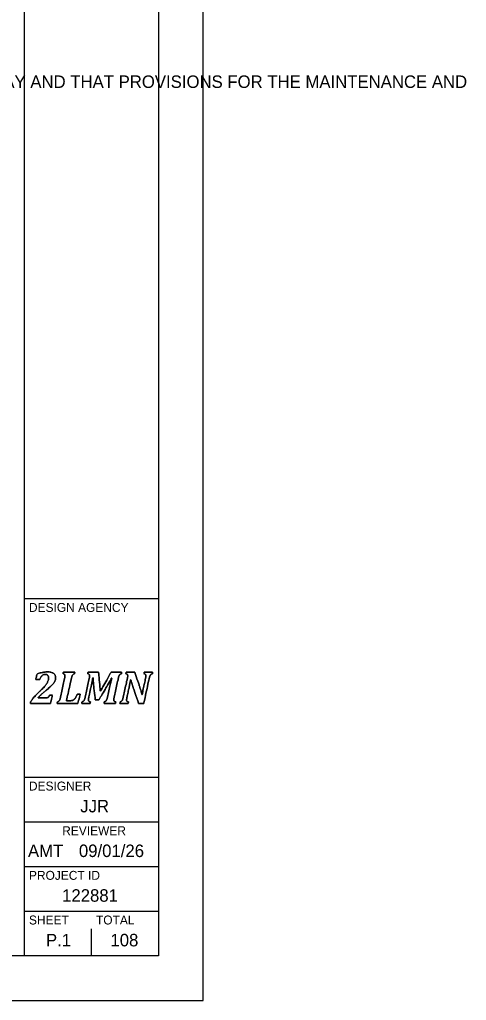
# Model space of a CAD drawing. Extents: x 0 to 36.9, y 0 to 22.
# Drawn here: x 31.95 to 36.95, y 0 to 10.98 of the extents above; entities that cross this region are included whole.
import ezdxf

# ---------------------------------------------------------------- set-up
doc = ezdxf.new("R2010")
doc.units = 0
for name, color, linetype in [('Default', 7, 'Continuous'), ('SH_Border', 7, 'Continuous'), ('SH_Cut_Line', 7, 'Continuous'), ('SH_Data', 7, 'Continuous')]:
    doc.layers.add(name, color=color, linetype=linetype)

msp = doc.modelspace()

# ---------------------------------------------------------------- linework, layer by layer
at = {"layer": 'SH_Border'}
for p, q in [((32, 0.5), (32, 21.5)), ((32, 4.5), (33.5, 4.5)), ((32, 2.5), (33.5, 2.5)), ((32, 2), (33.5, 2)), ((32, 1.5), (33.5, 1.5)), ((32, 1), (33.5, 1))]:
    msp.add_line(p, q, dxfattribs=at)
msp.add_lwpolyline([(1.5, 21.5), (33.5, 21.5), (33.5, 0.5), (1.5, 0.5)], close=True, dxfattribs=at)
at = {"layer": 'SH_Cut_Line'}
msp.add_lwpolyline([(0, 0), (34, 0), (34, 22), (0, 22)], close=True, dxfattribs=at)
at = {"layer": 'SH_Data'}
for p, q in [((32.75, 3.5), (32.75, 3.5)), ((32.75, 0.5), (32.75, 0.8)), ((32.375, 0.675), (32.375, 0.675))]:
    msp.add_line(p, q, dxfattribs=at)
for points in [[(32.237, 3.388), (32.246, 3.388), (32.253, 3.389), (32.258, 3.39), (32.263, 3.392), (32.267, 3.394), (32.27, 3.397), (32.273, 3.401), (32.277, 3.408), (32.281, 3.417), (32.281, 3.417), (32.312, 3.417), (32.312, 3.417), (32.312, 3.417), (32.29, 3.326), (32.29, 3.326), (32.29, 3.326), (32.066, 3.326), (32.066, 3.326), (32.066, 3.326), (32.069, 3.343), (32.069, 3.343), (32.078, 3.358), (32.091, 3.375), (32.106, 3.394), (32.122, 3.412), (32.144, 3.435), (32.172, 3.462), (32.197, 3.486), (32.217, 3.506), (32.23, 3.521), (32.243, 3.537), (32.253, 3.551), (32.259, 3.566), (32.266, 3.58), (32.269, 3.595), (32.269, 3.61), (32.269, 3.622), (32.266, 3.632), (32.26, 3.64), (32.253, 3.647), (32.245, 3.65), (32.234, 3.65), (32.22, 3.65), (32.208, 3.646), (32.198, 3.636), (32.188, 3.627), (32.18, 3.613), (32.172, 3.593), (32.172, 3.593), (32.126, 3.593), (32.126, 3.593), (32.126, 3.593), (32.14, 3.654), (32.14, 3.654), (32.166, 3.663), (32.188, 3.669), (32.205, 3.673), (32.223, 3.676), (32.24, 3.678), (32.258, 3.678), (32.278, 3.678), (32.295, 3.675), (32.309, 3.669), (32.322, 3.664), (32.332, 3.656), (32.339, 3.646), (32.345, 3.637), (32.348, 3.626), (32.348, 3.613), (32.348, 3.602), (32.346, 3.591), (32.342, 3.581), (32.339, 3.571), (32.333, 3.56), (32.324, 3.549), (32.315, 3.539), (32.304, 3.526), (32.289, 3.513), (32.275, 3.499), (32.254, 3.482), (32.228, 3.46), (32.216, 3.45), (32.202, 3.438), (32.188, 3.425), (32.174, 3.412), (32.162, 3.4), (32.154, 3.391), (32.154, 3.391), (32.153, 3.388), (32.153, 3.388), (32.153, 3.388), (32.237, 3.388), (32.237, 3.388)], [(32.237, 3.388), (32.237, 3.388), (32.153, 3.388), (32.153, 3.388), (32.153, 3.388), (32.154, 3.391), (32.154, 3.391), (32.162, 3.4), (32.174, 3.412), (32.188, 3.425), (32.202, 3.438), (32.216, 3.45), (32.228, 3.46), (32.254, 3.482), (32.275, 3.499), (32.289, 3.513), (32.304, 3.526), (32.315, 3.539), (32.324, 3.549), (32.333, 3.56), (32.339, 3.571), (32.342, 3.581), (32.346, 3.591), (32.348, 3.602), (32.348, 3.613), (32.348, 3.626), (32.345, 3.637), (32.339, 3.646), (32.332, 3.656), (32.322, 3.664), (32.309, 3.669), (32.295, 3.675), (32.278, 3.678), (32.258, 3.678), (32.24, 3.678), (32.223, 3.676), (32.205, 3.673), (32.188, 3.669), (32.166, 3.663), (32.14, 3.654), (32.14, 3.654), (32.126, 3.593), (32.126, 3.593), (32.126, 3.593), (32.172, 3.593), (32.172, 3.593), (32.18, 3.613), (32.188, 3.627), (32.198, 3.636), (32.208, 3.646), (32.22, 3.65), (32.234, 3.65), (32.245, 3.65), (32.253, 3.647), (32.26, 3.64), (32.266, 3.632), (32.269, 3.622), (32.269, 3.61), (32.269, 3.595), (32.266, 3.58), (32.259, 3.566), (32.253, 3.551), (32.243, 3.537), (32.23, 3.521), (32.217, 3.506), (32.197, 3.486), (32.172, 3.462), (32.144, 3.435), (32.122, 3.412), (32.106, 3.394), (32.091, 3.375), (32.078, 3.358), (32.069, 3.343), (32.069, 3.343), (32.066, 3.326), (32.066, 3.326), (32.066, 3.326), (32.29, 3.326), (32.29, 3.326), (32.29, 3.326), (32.312, 3.417), (32.312, 3.417), (32.312, 3.417), (32.281, 3.417), (32.281, 3.417), (32.277, 3.408), (32.273, 3.401), (32.27, 3.397), (32.267, 3.394), (32.263, 3.392), (32.258, 3.39), (32.253, 3.389), (32.246, 3.388), (32.237, 3.388)], [(32.518, 3.356), (32.527, 3.356), (32.533, 3.357), (32.538, 3.358), (32.542, 3.36), (32.546, 3.362), (32.55, 3.365), (32.554, 3.368), (32.558, 3.372), (32.562, 3.377), (32.567, 3.382), (32.571, 3.388), (32.576, 3.397), (32.58, 3.405), (32.585, 3.415), (32.589, 3.427), (32.589, 3.427), (32.624, 3.427), (32.624, 3.427), (32.624, 3.427), (32.598, 3.326), (32.598, 3.326), (32.598, 3.326), (32.365, 3.326), (32.365, 3.326), (32.365, 3.326), (32.369, 3.343), (32.369, 3.343), (32.376, 3.345), (32.381, 3.348), (32.385, 3.351), (32.389, 3.355), (32.392, 3.36), (32.395, 3.366), (32.398, 3.373), (32.4, 3.382), (32.403, 3.395), (32.403, 3.395), (32.449, 3.605), (32.449, 3.605), (32.452, 3.615), (32.453, 3.625), (32.453, 3.635), (32.453, 3.642), (32.451, 3.647), (32.448, 3.651), (32.444, 3.654), (32.439, 3.656), (32.432, 3.657), (32.432, 3.657), (32.435, 3.674), (32.435, 3.674), (32.435, 3.674), (32.563, 3.674), (32.563, 3.674), (32.563, 3.674), (32.559, 3.657), (32.559, 3.657), (32.552, 3.655), (32.547, 3.652), (32.543, 3.649), (32.539, 3.645), (32.536, 3.64), (32.533, 3.634), (32.531, 3.627), (32.528, 3.618), (32.525, 3.605), (32.525, 3.605), (32.47, 3.356), (32.47, 3.356), (32.47, 3.356), (32.518, 3.356), (32.518, 3.356)], [(32.518, 3.356), (32.518, 3.356), (32.47, 3.356), (32.47, 3.356), (32.47, 3.356), (32.525, 3.605), (32.525, 3.605), (32.528, 3.618), (32.531, 3.627), (32.533, 3.634), (32.536, 3.64), (32.539, 3.645), (32.543, 3.649), (32.547, 3.652), (32.552, 3.655), (32.559, 3.657), (32.559, 3.657), (32.563, 3.674), (32.563, 3.674), (32.563, 3.674), (32.435, 3.674), (32.435, 3.674), (32.435, 3.674), (32.432, 3.657), (32.432, 3.657), (32.439, 3.656), (32.444, 3.654), (32.448, 3.651), (32.451, 3.647), (32.453, 3.642), (32.453, 3.635), (32.453, 3.625), (32.452, 3.615), (32.449, 3.605), (32.449, 3.605), (32.403, 3.395), (32.403, 3.395), (32.4, 3.382), (32.398, 3.373), (32.395, 3.366), (32.392, 3.36), (32.389, 3.355), (32.385, 3.351), (32.381, 3.348), (32.376, 3.345), (32.369, 3.343), (32.369, 3.343), (32.365, 3.326), (32.365, 3.326), (32.365, 3.326), (32.598, 3.326), (32.598, 3.326), (32.598, 3.326), (32.624, 3.427), (32.624, 3.427), (32.624, 3.427), (32.589, 3.427), (32.589, 3.427), (32.585, 3.415), (32.58, 3.405), (32.576, 3.397), (32.571, 3.388), (32.567, 3.382), (32.562, 3.377), (32.558, 3.372), (32.554, 3.368), (32.55, 3.365), (32.546, 3.362), (32.542, 3.36), (32.538, 3.358), (32.533, 3.357), (32.527, 3.356), (32.518, 3.356)], [(32.829, 3.674), (32.829, 3.674), (32.849, 3.461), (32.849, 3.461), (32.849, 3.461), (32.969, 3.674), (32.969, 3.674), (32.969, 3.674), (33.087, 3.674), (33.087, 3.674), (33.087, 3.674), (33.084, 3.657), (33.084, 3.657), (33.077, 3.655), (33.071, 3.652), (33.067, 3.649), (33.064, 3.645), (33.06, 3.64), (33.058, 3.634), (33.055, 3.627), (33.052, 3.618), (33.05, 3.605), (33.05, 3.605), (33.003, 3.395), (33.003, 3.395), (33.002, 3.39), (33.002, 3.387), (33.001, 3.384), (33.001, 3.382), (33.001, 3.379), (33, 3.376), (33, 3.373), (33, 3.369), (33, 3.365), (33, 3.358), (33.002, 3.353), (33.005, 3.349), (33.008, 3.346), (33.014, 3.344), (33.021, 3.343), (33.021, 3.343), (33.018, 3.326), (33.018, 3.326), (33.018, 3.326), (32.89, 3.326), (32.89, 3.326), (32.89, 3.326), (32.893, 3.343), (32.893, 3.343), (32.9, 3.345), (32.906, 3.348), (32.91, 3.351), (32.914, 3.355), (32.917, 3.36), (32.919, 3.366), (32.922, 3.373), (32.925, 3.382), (32.928, 3.395), (32.928, 3.395), (32.951, 3.502), (32.951, 3.502), (32.954, 3.513), (32.957, 3.529), (32.962, 3.548), (32.967, 3.568), (32.972, 3.588), (32.978, 3.609), (32.978, 3.609), (32.973, 3.609), (32.973, 3.609), (32.965, 3.594), (32.957, 3.579), (32.948, 3.563), (32.948, 3.563), (32.833, 3.364), (32.833, 3.364), (32.833, 3.364), (32.792, 3.364), (32.792, 3.364), (32.792, 3.364), (32.775, 3.518), (32.775, 3.518), (32.773, 3.537), (32.772, 3.554), (32.77, 3.569), (32.769, 3.583), (32.768, 3.597), (32.768, 3.611), (32.768, 3.611), (32.764, 3.611), (32.764, 3.611), (32.761, 3.596), (32.758, 3.578), (32.755, 3.558), (32.751, 3.538), (32.747, 3.521), (32.744, 3.507), (32.744, 3.507), (32.72, 3.395), (32.72, 3.395), (32.719, 3.39), (32.718, 3.387), (32.718, 3.384), (32.717, 3.382), (32.717, 3.379), (32.717, 3.376), (32.717, 3.373), (32.716, 3.369), (32.716, 3.365), (32.716, 3.358), (32.718, 3.353), (32.721, 3.349), (32.725, 3.346), (32.73, 3.344), (32.738, 3.343), (32.738, 3.343), (32.734, 3.326), (32.734, 3.326), (32.734, 3.326), (32.641, 3.326), (32.641, 3.326), (32.641, 3.326), (32.644, 3.343), (32.644, 3.343), (32.651, 3.345), (32.657, 3.348), (32.661, 3.351), (32.665, 3.355), (32.668, 3.36), (32.67, 3.366), (32.673, 3.373), (32.676, 3.382), (32.679, 3.395), (32.679, 3.395), (32.725, 3.605), (32.725, 3.605), (32.727, 3.615), (32.728, 3.625), (32.728, 3.635), (32.728, 3.642), (32.727, 3.647), (32.723, 3.651), (32.72, 3.654), (32.715, 3.656), (32.707, 3.657), (32.707, 3.657), (32.711, 3.674), (32.711, 3.674), (32.711, 3.674), (32.829, 3.674), (32.829, 3.674)], [(32.829, 3.674), (32.829, 3.674), (32.711, 3.674), (32.711, 3.674), (32.711, 3.674), (32.707, 3.657), (32.707, 3.657), (32.715, 3.656), (32.72, 3.654), (32.723, 3.651), (32.727, 3.647), (32.728, 3.642), (32.728, 3.635), (32.728, 3.625), (32.727, 3.615), (32.725, 3.605), (32.725, 3.605), (32.679, 3.395), (32.679, 3.395), (32.676, 3.382), (32.673, 3.373), (32.67, 3.366), (32.668, 3.36), (32.665, 3.355), (32.661, 3.351), (32.657, 3.348), (32.651, 3.345), (32.644, 3.343), (32.644, 3.343), (32.641, 3.326), (32.641, 3.326), (32.641, 3.326), (32.734, 3.326), (32.734, 3.326), (32.734, 3.326), (32.738, 3.343), (32.738, 3.343), (32.73, 3.344), (32.725, 3.346), (32.721, 3.349), (32.718, 3.353), (32.716, 3.358), (32.716, 3.365), (32.716, 3.369), (32.717, 3.373), (32.717, 3.376), (32.717, 3.379), (32.717, 3.382), (32.718, 3.384), (32.718, 3.387), (32.719, 3.39), (32.72, 3.395), (32.72, 3.395), (32.744, 3.507), (32.744, 3.507), (32.747, 3.521), (32.751, 3.538), (32.755, 3.558), (32.758, 3.578), (32.761, 3.596), (32.764, 3.611), (32.764, 3.611), (32.768, 3.611), (32.768, 3.611), (32.768, 3.597), (32.769, 3.583), (32.77, 3.569), (32.772, 3.554), (32.773, 3.537), (32.775, 3.518), (32.775, 3.518), (32.792, 3.364), (32.792, 3.364), (32.792, 3.364), (32.833, 3.364), (32.833, 3.364), (32.833, 3.364), (32.948, 3.563), (32.948, 3.563), (32.957, 3.579), (32.965, 3.594), (32.973, 3.609), (32.973, 3.609), (32.978, 3.609), (32.978, 3.609), (32.972, 3.588), (32.967, 3.568), (32.962, 3.548), (32.957, 3.529), (32.954, 3.513), (32.951, 3.502), (32.951, 3.502), (32.928, 3.395), (32.928, 3.395), (32.925, 3.382), (32.922, 3.373), (32.919, 3.366), (32.917, 3.36), (32.914, 3.355), (32.91, 3.351), (32.906, 3.348), (32.9, 3.345), (32.893, 3.343), (32.893, 3.343), (32.89, 3.326), (32.89, 3.326), (32.89, 3.326), (33.018, 3.326), (33.018, 3.326), (33.018, 3.326), (33.021, 3.343), (33.021, 3.343), (33.014, 3.344), (33.008, 3.346), (33.005, 3.349), (33.002, 3.353), (33, 3.358), (33, 3.365), (33, 3.369), (33, 3.373), (33, 3.376), (33.001, 3.379), (33.001, 3.382), (33.001, 3.384), (33.002, 3.387), (33.002, 3.39), (33.003, 3.395), (33.003, 3.395), (33.05, 3.605), (33.05, 3.605), (33.052, 3.618), (33.055, 3.627), (33.058, 3.634), (33.06, 3.64), (33.064, 3.645), (33.067, 3.649), (33.071, 3.652), (33.077, 3.655), (33.084, 3.657), (33.084, 3.657), (33.087, 3.674), (33.087, 3.674), (33.087, 3.674), (32.969, 3.674), (32.969, 3.674), (32.969, 3.674), (32.849, 3.461), (32.849, 3.461), (32.849, 3.461), (32.829, 3.674), (32.829, 3.674)], [(33.137, 3.674), (33.137, 3.674), (33.234, 3.674), (33.234, 3.674), (33.234, 3.674), (33.283, 3.53), (33.283, 3.53), (33.296, 3.49), (33.307, 3.456), (33.315, 3.426), (33.315, 3.426), (33.318, 3.426), (33.318, 3.426), (33.323, 3.455), (33.329, 3.488), (33.337, 3.523), (33.337, 3.523), (33.355, 3.605), (33.355, 3.605), (33.357, 3.615), (33.358, 3.625), (33.358, 3.635), (33.358, 3.642), (33.357, 3.647), (33.353, 3.651), (33.35, 3.654), (33.345, 3.656), (33.337, 3.657), (33.337, 3.657), (33.341, 3.674), (33.341, 3.674), (33.341, 3.674), (33.434, 3.674), (33.434, 3.674), (33.434, 3.674), (33.431, 3.657), (33.431, 3.657), (33.424, 3.655), (33.418, 3.652), (33.414, 3.649), (33.41, 3.645), (33.407, 3.64), (33.405, 3.634), (33.402, 3.627), (33.399, 3.618), (33.396, 3.605), (33.396, 3.605), (33.335, 3.326), (33.335, 3.326), (33.335, 3.326), (33.277, 3.326), (33.277, 3.326), (33.277, 3.326), (33.216, 3.504), (33.216, 3.504), (33.211, 3.518), (33.207, 3.531), (33.204, 3.543), (33.2, 3.556), (33.195, 3.571), (33.19, 3.59), (33.19, 3.59), (33.186, 3.59), (33.186, 3.59), (33.185, 3.579), (33.182, 3.563), (33.179, 3.543), (33.175, 3.523), (33.17, 3.501), (33.165, 3.478), (33.165, 3.478), (33.147, 3.395), (33.147, 3.395), (33.146, 3.39), (33.145, 3.387), (33.145, 3.384), (33.144, 3.382), (33.144, 3.379), (33.144, 3.376), (33.143, 3.373), (33.143, 3.369), (33.143, 3.365), (33.143, 3.358), (33.145, 3.353), (33.148, 3.349), (33.152, 3.346), (33.157, 3.344), (33.164, 3.343), (33.164, 3.343), (33.161, 3.326), (33.161, 3.326), (33.161, 3.326), (33.067, 3.326), (33.067, 3.326), (33.067, 3.326), (33.071, 3.343), (33.071, 3.343), (33.078, 3.345), (33.083, 3.348), (33.087, 3.351), (33.091, 3.355), (33.094, 3.36), (33.097, 3.366), (33.1, 3.373), (33.102, 3.382), (33.105, 3.395), (33.105, 3.395), (33.151, 3.605), (33.151, 3.605), (33.154, 3.615), (33.155, 3.625), (33.155, 3.635), (33.155, 3.642), (33.153, 3.647), (33.15, 3.651), (33.146, 3.654), (33.141, 3.656), (33.134, 3.657), (33.134, 3.657), (33.137, 3.674), (33.137, 3.674)], [(33.137, 3.674), (33.137, 3.674), (33.134, 3.657), (33.134, 3.657), (33.141, 3.656), (33.146, 3.654), (33.15, 3.651), (33.153, 3.647), (33.155, 3.642), (33.155, 3.635), (33.155, 3.625), (33.154, 3.615), (33.151, 3.605), (33.151, 3.605), (33.105, 3.395), (33.105, 3.395), (33.102, 3.382), (33.1, 3.373), (33.097, 3.366), (33.094, 3.36), (33.091, 3.355), (33.087, 3.351), (33.083, 3.348), (33.078, 3.345), (33.071, 3.343), (33.071, 3.343), (33.067, 3.326), (33.067, 3.326), (33.067, 3.326), (33.161, 3.326), (33.161, 3.326), (33.161, 3.326), (33.164, 3.343), (33.164, 3.343), (33.157, 3.344), (33.152, 3.346), (33.148, 3.349), (33.145, 3.353), (33.143, 3.358), (33.143, 3.365), (33.143, 3.369), (33.143, 3.373), (33.144, 3.376), (33.144, 3.379), (33.144, 3.382), (33.145, 3.384), (33.145, 3.387), (33.146, 3.39), (33.147, 3.395), (33.147, 3.395), (33.165, 3.478), (33.165, 3.478), (33.17, 3.501), (33.175, 3.523), (33.179, 3.543), (33.182, 3.563), (33.185, 3.579), (33.186, 3.59), (33.186, 3.59), (33.19, 3.59), (33.19, 3.59), (33.195, 3.571), (33.2, 3.556), (33.204, 3.543), (33.207, 3.531), (33.211, 3.518), (33.216, 3.504), (33.216, 3.504), (33.277, 3.326), (33.277, 3.326), (33.277, 3.326), (33.335, 3.326), (33.335, 3.326), (33.335, 3.326), (33.396, 3.605), (33.396, 3.605), (33.399, 3.618), (33.402, 3.627), (33.405, 3.634), (33.407, 3.64), (33.41, 3.645), (33.414, 3.649), (33.418, 3.652), (33.424, 3.655), (33.431, 3.657), (33.431, 3.657), (33.434, 3.674), (33.434, 3.674), (33.434, 3.674), (33.341, 3.674), (33.341, 3.674), (33.341, 3.674), (33.337, 3.657), (33.337, 3.657), (33.345, 3.656), (33.35, 3.654), (33.353, 3.651), (33.357, 3.647), (33.358, 3.642), (33.358, 3.635), (33.358, 3.625), (33.357, 3.615), (33.355, 3.605), (33.355, 3.605), (33.337, 3.523), (33.337, 3.523), (33.329, 3.488), (33.323, 3.455), (33.318, 3.426), (33.318, 3.426), (33.315, 3.426), (33.315, 3.426), (33.307, 3.456), (33.296, 3.49), (33.283, 3.53), (33.283, 3.53), (33.234, 3.674), (33.234, 3.674), (33.234, 3.674), (33.137, 3.674), (33.137, 3.674)]]:
    msp.add_open_spline(points, degree=3, dxfattribs=at)

# ---------------------------------------------------------------- texts
at = {"layer": 'Default'}
msp.add_text('REQUIRE THE CLOSING TO TRAFFIC OF THE HIGHWAY AND THAT PROVISIONS FOR THE MAINTENANCE AND', height=0.14, dxfattribs=at).set_placement((27, 10.217))
at = {"layer": 'SH_Data'}
for s, height, p in [('DESIGN AGENCY', 0.1, (32.05, 4.35)), ('DESIGNER', 0.1, (32.05, 2.35)), ('JJR', 0.14, (32.624, 2.105)), ('REVIEWER', 0.1, (32.422, 1.85)), ('AMT', 0.14, (32.039, 1.605)), ('09/01/26', 0.14, (32.609, 1.605)), ('PROJECT ID', 0.1, (32.05, 1.35)), ('122881', 0.14, (32.421, 1.105)), ('SHEET', 0.1, (32.05, 0.85)), ('TOTAL', 0.1, (32.8, 0.85)), ('P.1', 0.14, (32.24, 0.605)), ('108', 0.14, (32.962, 0.605))]:
    msp.add_text(s, height=height, dxfattribs=at).set_placement(p)

doc.saveas('drawing.dxf')
